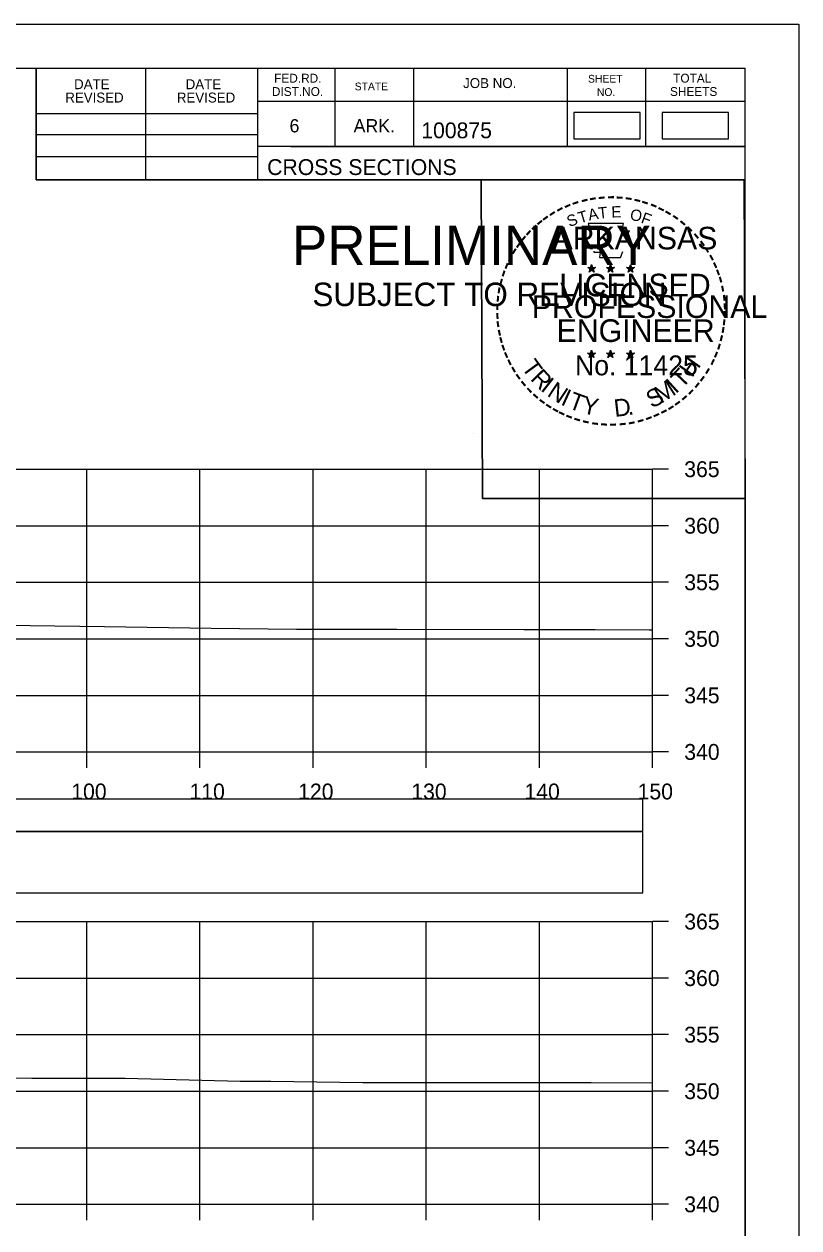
# Model space of a CAD drawing. Extents: x 1368122 to 1710785, y 373130 to 557566.
# Drawn here: x 1368783.3 to 1368851.8, y 375157.3 to 375263.7 of the extents above; entities that cross this region are included whole.
import ezdxf

# ---------------------------------------------------------------- set-up
doc = ezdxf.new("R2010")
doc.units = 0
for name, color, linetype in [('R_Alt Surface', 7, 'Continuous'), ('R_Axis', 7, 'Continuous'), ('R_Axis Annot', 7, 'Continuous'), ('R_Border', 7, 'Continuous'), ('R_Border PE', 7, 'Continuous'), ('R_Border Prem', 7, 'Continuous'), ('R_Drive', 7, 'Continuous'), ('R_Exist Surface', 7, 'Continuous'), ('R_Grid', 7, 'Continuous'), ('R_No Plot', 7, 'Continuous')]:
    doc.layers.add(name, color=color, linetype=linetype)

msp = doc.modelspace()

# ---------------------------------------------------------------- linework, layer by layer
at = {"layer": 'R_Alt Surface'}
for points in [[(1368539.73, 375192.34), (1368838.03, 375192.34), (1368838.03, 375195.16), (1368539.73, 375195.16)], [(1368539.73, 375186.88), (1368838.03, 375186.88), (1368838.03, 375192.29), (1368539.73, 375192.29)]]:
    msp.add_lwpolyline(points, close=True, dxfattribs=at)
at = {"layer": 'R_Axis'}
for p, q in [((1368838.88, 375199.35), (1368838.88, 375224.35)), ((1368840.28, 375224.35), (1368838.88, 375224.35)), ((1368840.28, 375219.35), (1368838.88, 375219.35)), ((1368840.28, 375214.35), (1368838.88, 375214.35)), ((1368840.28, 375209.35), (1368838.88, 375209.35)), ((1368840.28, 375204.35), (1368838.88, 375204.35)), ((1368538.88, 375199.35), (1368838.88, 375199.35)), ((1368788.88, 375197.95), (1368788.88, 375199.35)), ((1368798.88, 375197.95), (1368798.88, 375199.35)), ((1368808.88, 375197.95), (1368808.88, 375199.35)), ((1368818.88, 375197.95), (1368818.88, 375199.35)), ((1368828.88, 375197.95), (1368828.88, 375199.35)), ((1368838.88, 375197.95), (1368838.88, 375199.35)), ((1368840.28, 375199.35), (1368838.88, 375199.35)), ((1368838.88, 375159.35), (1368838.88, 375184.35)), ((1368840.28, 375184.35), (1368838.88, 375184.35)), ((1368840.28, 375179.35), (1368838.88, 375179.35)), ((1368840.28, 375174.35), (1368838.88, 375174.35)), ((1368840.28, 375169.35), (1368838.88, 375169.35)), ((1368840.28, 375164.35), (1368838.88, 375164.35)), ((1368538.88, 375159.35), (1368838.88, 375159.35)), ((1368788.88, 375157.95), (1368788.88, 375159.35)), ((1368798.88, 375157.95), (1368798.88, 375159.35)), ((1368808.88, 375157.95), (1368808.88, 375159.35)), ((1368818.88, 375157.95), (1368818.88, 375159.35)), ((1368828.88, 375157.95), (1368828.88, 375159.35)), ((1368838.88, 375157.95), (1368838.88, 375159.35)), ((1368840.28, 375159.35), (1368838.88, 375159.35))]:
    msp.add_line(p, q, dxfattribs=at)
at = {"layer": 'R_Border'}
for p, q in [((1368530.88, 375259.81), (1368847.06, 375259.81)), ((1368784.42, 375249.93), (1368784.42, 375259.81)), ((1368794.1, 375249.93), (1368794.1, 375259.81)), ((1368803.96, 375259.81), (1368803.96, 375249.93)), ((1368810.8, 375259.81), (1368810.8, 375252.87)), ((1368817.74, 375259.81), (1368817.74, 375252.87)), ((1368831.32, 375259.81), (1368831.32, 375252.87)), ((1368838.26, 375259.81), (1368838.26, 375252.87)), ((1368847.06, 375054.35), (1368847.06, 375259.81)), ((1368847.06, 375256.87), (1368803.96, 375256.87)), ((1368847.06, 375256.89), (1368847.06, 375256.89)), ((1368784.42, 375255.79), (1368803.96, 375255.79)), ((1368784.42, 375253.93), (1368803.96, 375253.93)), ((1368847.06, 375252.87), (1368803.96, 375252.87)), ((1368806.92, 375252.87), (1368847.06, 375252.87)), ((1368784.42, 375251.99), (1368803.96, 375251.99)), ((1368847.06, 375249.93), (1368784.42, 375249.93))]:
    msp.add_line(p, q, dxfattribs=at)
at = {"layer": 'R_Border PE'}
for p, q in [((1368833.15, 375242.19), (1368833.49, 375242.08)), ((1368833.15, 375242.19), (1368833.4, 375242.14)), ((1368833.15, 375242.19), (1368833.38, 375242.06)), ((1368833.28, 375241.78), (1368833.49, 375242.08)), ((1368833.28, 375241.78), (1368833.4, 375242.02)), ((1368833.28, 375241.78), (1368833.49, 375242)), ((1368833.49, 375242.44), (1368833.45, 375242.19)), ((1368833.49, 375242.08), (1368833.49, 375242.44)), ((1368833.49, 375242.44), (1368833.54, 375242.19)), ((1368833.84, 375242.19), (1368833.49, 375242.08)), ((1368833.71, 375241.78), (1368833.49, 375242.08)), ((1368833.71, 375241.78), (1368833.49, 375241.99)), ((1368833.84, 375242.19), (1368833.56, 375242.14)), ((1368833.71, 375241.78), (1368833.57, 375242.07)), ((1368833.84, 375242.19), (1368833.64, 375242.08)), ((1368834.82, 375242.19), (1368835.16, 375242.08)), ((1368834.82, 375242.19), (1368835.07, 375242.14)), ((1368834.82, 375242.19), (1368835.05, 375242.06)), ((1368834.95, 375241.78), (1368835.16, 375242.08)), ((1368834.95, 375241.78), (1368835.07, 375242.02)), ((1368834.95, 375241.78), (1368835.16, 375242)), ((1368835.16, 375242.44), (1368835.12, 375242.19)), ((1368835.16, 375242.08), (1368835.16, 375242.44)), ((1368835.16, 375242.44), (1368835.21, 375242.19)), ((1368835.51, 375242.19), (1368835.16, 375242.08)), ((1368835.38, 375241.78), (1368835.16, 375242.08)), ((1368835.38, 375241.78), (1368835.16, 375241.99)), ((1368835.51, 375242.19), (1368835.23, 375242.14)), ((1368835.38, 375241.78), (1368835.24, 375242.07)), ((1368835.51, 375242.19), (1368835.31, 375242.08)), ((1368836.58, 375242.17), (1368836.93, 375242.06)), ((1368836.58, 375242.17), (1368836.83, 375242.13)), ((1368836.58, 375242.17), (1368836.82, 375242.05)), ((1368836.71, 375241.77), (1368836.93, 375242.06)), ((1368836.71, 375241.77), (1368836.84, 375242.01)), ((1368836.71, 375241.77), (1368836.93, 375241.98)), ((1368836.93, 375242.43), (1368836.89, 375242.18)), ((1368836.93, 375242.06), (1368836.93, 375242.43)), ((1368836.93, 375242.43), (1368836.98, 375242.18)), ((1368837.28, 375242.17), (1368836.93, 375242.06)), ((1368837.14, 375241.77), (1368836.93, 375242.06)), ((1368837.14, 375241.77), (1368836.93, 375241.98)), ((1368837.28, 375242.17), (1368836.99, 375242.13)), ((1368837.14, 375241.77), (1368837, 375242.06)), ((1368837.28, 375242.17), (1368837.07, 375242.07)), ((1368833.14, 375234.61), (1368833.49, 375234.5)), ((1368833.14, 375234.61), (1368833.39, 375234.57)), ((1368833.14, 375234.61), (1368833.38, 375234.49)), ((1368833.27, 375234.21), (1368833.49, 375234.5)), ((1368833.27, 375234.21), (1368833.4, 375234.45)), ((1368833.27, 375234.21), (1368833.49, 375234.42)), ((1368833.49, 375234.87), (1368833.45, 375234.62)), ((1368833.49, 375234.5), (1368833.49, 375234.87)), ((1368833.49, 375234.87), (1368833.54, 375234.62)), ((1368833.84, 375234.61), (1368833.49, 375234.5)), ((1368833.7, 375234.21), (1368833.49, 375234.5)), ((1368833.7, 375234.21), (1368833.49, 375234.42)), ((1368833.84, 375234.61), (1368833.55, 375234.56)), ((1368833.7, 375234.21), (1368833.57, 375234.5)), ((1368833.84, 375234.61), (1368833.63, 375234.51)), ((1368834.81, 375234.61), (1368835.16, 375234.5)), ((1368834.81, 375234.61), (1368835.06, 375234.57)), ((1368834.81, 375234.61), (1368835.05, 375234.49)), ((1368834.94, 375234.21), (1368835.16, 375234.5)), ((1368834.94, 375234.21), (1368835.07, 375234.45)), ((1368834.94, 375234.21), (1368835.16, 375234.42)), ((1368835.16, 375234.87), (1368835.12, 375234.62)), ((1368835.16, 375234.5), (1368835.16, 375234.87)), ((1368835.16, 375234.87), (1368835.21, 375234.62)), ((1368835.51, 375234.61), (1368835.16, 375234.5)), ((1368835.37, 375234.21), (1368835.16, 375234.5)), ((1368835.37, 375234.21), (1368835.16, 375234.42)), ((1368835.51, 375234.61), (1368835.22, 375234.56)), ((1368835.37, 375234.21), (1368835.24, 375234.5)), ((1368835.51, 375234.61), (1368835.3, 375234.51)), ((1368836.58, 375234.6), (1368836.93, 375234.49)), ((1368836.58, 375234.6), (1368836.83, 375234.56)), ((1368836.58, 375234.6), (1368836.81, 375234.48)), ((1368836.71, 375234.2), (1368836.93, 375234.49)), ((1368836.71, 375234.2), (1368836.84, 375234.44)), ((1368836.71, 375234.2), (1368836.92, 375234.41)), ((1368836.93, 375234.86), (1368836.89, 375234.61)), ((1368837.14, 375234.2), (1368836.92, 375234.41)), ((1368836.93, 375234.49), (1368836.93, 375234.86)), ((1368836.93, 375234.86), (1368836.98, 375234.61)), ((1368837.27, 375234.6), (1368836.93, 375234.49)), ((1368837.14, 375234.2), (1368836.93, 375234.49)), ((1368837.27, 375234.6), (1368836.99, 375234.55)), ((1368837.14, 375234.2), (1368837, 375234.49)), ((1368837.27, 375234.6), (1368837.07, 375234.5))]:
    msp.add_line(p, q, dxfattribs=at)
for points in [[(1368833.19, 375246.06), (1368833.46, 375245.24)], [(1368836.7, 375245.14), (1368836.84, 375245.43), (1368836.15, 375245.4), (1368836.3, 375246.06), (1368833.19, 375246.06)], [(1368833.68, 375243.64), (1368833.68, 375243.55), (1368834.24, 375243.54), (1368834.19, 375243.06), (1368836.06, 375243.06), (1368836.26, 375243.6)], [(1368833.49, 375242.44), (1368833.71, 375241.78), (1368833.15, 375242.19), (1368833.84, 375242.19), (1368833.28, 375241.78), (1368833.49, 375242.44)], [(1368835.16, 375242.44), (1368835.38, 375241.78), (1368834.82, 375242.19), (1368835.51, 375242.19), (1368834.95, 375241.78), (1368835.16, 375242.44)], [(1368836.93, 375242.43), (1368837.14, 375241.77), (1368836.58, 375242.17), (1368837.28, 375242.17), (1368836.71, 375241.77), (1368836.93, 375242.43)], [(1368833.49, 375234.87), (1368833.7, 375234.21), (1368833.14, 375234.61), (1368833.84, 375234.61), (1368833.27, 375234.21), (1368833.49, 375234.87)], [(1368835.16, 375234.87), (1368835.37, 375234.21), (1368834.81, 375234.61), (1368835.51, 375234.61), (1368834.94, 375234.21), (1368835.16, 375234.87)], [(1368836.93, 375234.86), (1368837.14, 375234.2), (1368836.58, 375234.6), (1368837.27, 375234.6), (1368836.71, 375234.2), (1368836.93, 375234.86)]]:
    msp.add_lwpolyline(points, dxfattribs=at)
for centre, radius in [((1368833.49, 375242.07), 0.172), ((1368833.49, 375242.07), 0.145), ((1368833.49, 375242.07), 0.116), ((1368833.49, 375242.07), 0.0991), ((1368833.49, 375242.07), 0.0747), ((1368833.49, 375242.07), 0.0495), ((1368833.49, 375242.07), 0.0296), ((1368835.16, 375242.07), 0.172), ((1368835.16, 375242.07), 0.145), ((1368835.16, 375242.07), 0.116), ((1368835.16, 375242.07), 0.0991), ((1368835.16, 375242.07), 0.0747), ((1368835.16, 375242.07), 0.0495), ((1368835.16, 375242.07), 0.0296), ((1368836.93, 375242.06), 0.172), ((1368836.93, 375242.06), 0.145), ((1368836.93, 375242.06), 0.116), ((1368836.93, 375242.06), 0.0991), ((1368836.93, 375242.06), 0.0747), ((1368836.93, 375242.06), 0.0495), ((1368836.93, 375242.06), 0.0296), ((1368833.49, 375234.5), 0.172), ((1368833.49, 375234.5), 0.145), ((1368833.49, 375234.5), 0.116), ((1368833.49, 375234.5), 0.0991), ((1368833.49, 375234.5), 0.0747), ((1368833.49, 375234.5), 0.0495), ((1368833.49, 375234.5), 0.0296), ((1368835.16, 375234.5), 0.172), ((1368835.16, 375234.5), 0.145), ((1368835.16, 375234.5), 0.116), ((1368835.16, 375234.5), 0.0991), ((1368835.16, 375234.5), 0.0747), ((1368835.16, 375234.5), 0.0495), ((1368835.16, 375234.5), 0.0296), ((1368836.93, 375234.49), 0.172), ((1368836.93, 375234.49), 0.145), ((1368836.93, 375234.49), 0.116), ((1368836.93, 375234.49), 0.0991), ((1368836.93, 375234.49), 0.0747), ((1368836.93, 375234.49), 0.0495), ((1368836.93, 375234.49), 0.0296)]:
    msp.add_circle(centre, radius, dxfattribs=at)
at = {"layer": 'R_Drive'}
for points in [[(1368831.93, 375253.57), (1368837.77, 375253.57), (1368837.77, 375255.88), (1368831.93, 375255.88)], [(1368839.74, 375253.57), (1368845.58, 375253.57), (1368845.58, 375255.88), (1368839.74, 375255.88)]]:
    msp.add_lwpolyline(points, close=True, dxfattribs=at)
at = {"layer": 'R_Exist Surface'}
for points in [[(1368731.13, 375212.31), (1368743.96, 375211.83), (1368745.31, 375211.78), (1368746.01, 375211.76), (1368746.56, 375211.75), (1368752.58, 375211.61), (1368753.7, 375211.48), (1368759.44, 375211.17), (1368762.31, 375211.12), (1368769.98, 375210.82), (1368772.66, 375210.76), (1368774.76, 375210.66), (1368783.88, 375210.54), (1368790.45, 375210.45), (1368799.86, 375210.29), (1368807.4, 375210.2), (1368816.28, 375210.2), (1368827.49, 375210.17), (1368833.8, 375210.17), (1368838.57, 375210.14), (1368838.88, 375210.14)], [(1368740.7, 375171.86), (1368747.9, 375171.57), (1368763.84, 375171.02), (1368766.69, 375170.91), (1368767.25, 375170.93), (1368769.25, 375170.84), (1368770.02, 375170.82), (1368774.17, 375170.74), (1368779.38, 375170.58), (1368784.03, 375170.5), (1368792.26, 375170.51), (1368802.45, 375170.23), (1368805.14, 375170.23), (1368813.29, 375170.11), (1368819.21, 375170.11), (1368819.86, 375170.11), (1368833.46, 375170.12), (1368838.88, 375170.08)]]:
    msp.add_lwpolyline(points, dxfattribs=at)
at = {"layer": 'R_Grid'}
for p, q in [((1368538.88, 375224.35), (1368838.88, 375224.35)), ((1368788.88, 375199.35), (1368788.88, 375224.35)), ((1368798.88, 375199.35), (1368798.88, 375224.35)), ((1368808.88, 375199.35), (1368808.88, 375224.35)), ((1368818.88, 375199.35), (1368818.88, 375224.35)), ((1368828.88, 375199.35), (1368828.88, 375224.35)), ((1368838.88, 375199.35), (1368838.88, 375224.35)), ((1368538.88, 375219.35), (1368838.88, 375219.35)), ((1368538.88, 375214.35), (1368838.88, 375214.35)), ((1368538.88, 375209.35), (1368838.88, 375209.35)), ((1368538.88, 375204.35), (1368838.88, 375204.35)), ((1368538.88, 375199.35), (1368838.88, 375199.35)), ((1368538.88, 375184.35), (1368838.88, 375184.35)), ((1368788.88, 375159.35), (1368788.88, 375184.35)), ((1368798.88, 375159.35), (1368798.88, 375184.35)), ((1368808.88, 375159.35), (1368808.88, 375184.35)), ((1368818.88, 375159.35), (1368818.88, 375184.35)), ((1368828.88, 375159.35), (1368828.88, 375184.35)), ((1368838.88, 375159.35), (1368838.88, 375184.35)), ((1368538.88, 375179.35), (1368838.88, 375179.35)), ((1368538.88, 375174.35), (1368838.88, 375174.35)), ((1368538.88, 375169.35), (1368838.88, 375169.35)), ((1368538.88, 375164.35), (1368838.88, 375164.35)), ((1368538.88, 375159.35), (1368838.88, 375159.35))]:
    msp.add_line(p, q, dxfattribs=at)
at = {"layer": 'R_No Plot'}
for p, q in [((1368518.48, 375263.71), (1368851.81, 375263.71)), ((1368823.09, 375227.48), (1368823.09, 375227.48))]:
    msp.add_line(p, q, dxfattribs=at)
for points in [[(1368518.47, 375263.71), (1368851.81, 375263.71), (1368851.81, 375050.37), (1368518.47, 375050.37)], [(1368764.8, 375259.81), (1368784.42, 375259.81), (1368784.42, 375249.93), (1368800.53, 375249.93), (1368823.73, 375249.93), (1368823.85, 375221.77), (1368847.06, 375221.77), (1368847.06, 375054.35), (1368530.88, 375054.35), (1368530.88, 375259.81)], [(1368823.73, 375249.93), (1368846.94, 375249.93), (1368847.06, 375221.77), (1368823.85, 375221.77)]]:
    msp.add_lwpolyline(points, close=True, dxfattribs=at)

# ---------------------------------------------------------------- texts
at = {"layer": 'R_Axis Annot'}
for s, p in [('365', (1368841.68, 375223.65)), ('360', (1368841.68, 375218.65)), ('355', (1368841.68, 375213.65)), ('350', (1368841.68, 375208.65)), ('345', (1368841.68, 375203.65)), ('340', (1368841.68, 375198.65)), ('100', (1368787.51, 375195.15)), ('110', (1368797.96, 375195.15)), ('120', (1368807.56, 375195.15)), ('130', (1368817.56, 375195.15)), ('140', (1368827.56, 375195.15)), ('150', (1368837.56, 375195.15)), ('365', (1368841.68, 375183.65)), ('360', (1368841.68, 375178.65)), ('355', (1368841.68, 375173.65)), ('350', (1368841.68, 375168.65)), ('345', (1368841.68, 375163.65)), ('340', (1368841.68, 375158.65))]:
    msp.add_text(s, height=1.4, dxfattribs=at).set_placement(p)
at = {"layer": 'R_Border'}
for s, height, p in [('DATE', 0.879, (1368787.76, 375257.95)), ('DATE', 0.879, (1368797.62, 375257.95)), ('FED.RD.', 0.782, (1368805.44, 375258.53)), ('STATE', 0.684, (1368812.56, 375257.85)), ('JOB NO.', 0.879, (1368822.14, 375258.05)), ('SHEET', 0.684, (1368833.18, 375258.53)), ('TOTAL', 0.782, (1368840.7, 375258.53)), ('REVISED', 0.879, (1368786.98, 375256.77)), ('REVISED', 0.879, (1368796.84, 375256.77)), ('DIST.NO.', 0.782, (1368805.24, 375257.35)), ('NO.', 0.684, (1368833.96, 375257.35)), ('SHEETS', 0.782, (1368840.42, 375257.35)), ('6', 1.17, (1368806.8, 375254.13)), ('ARK.', 1.172, (1368812.46, 375254.13)), ('100875', 1.4, (1368818.44, 375253.61)), ('CROSS SECTIONS', 1.4, (1368804.82, 375250.36))]:
    msp.add_text(s, height=height, rotation=360, dxfattribs=at).set_placement(p)
at = {"layer": 'R_Border PE'}
for s, height, rotation, p in [('-', 1.6, 19.1761, (1368831.93, 375247.19)), ('-', 1.6, 13.6301, (1368832.68, 375247.43)), ('-', 1.6, 10.2193, (1368833.36, 375247.59)), ('-', 1.6, 5.8968, (1368834.09, 375247.7)), ('-', 1.6, 0.1862, (1368834.86, 375247.78)), ('-', 1.6, 357.743, (1368835.59, 375247.76)), ('-', 1.6, 352.1617, (1368836.33, 375247.71)), ('-', 1.6, 347.2049, (1368837.05, 375247.59)), ('-', 1.6, 342.3362, (1368837.68, 375247.44)), ('-', 1.6, 337.8551, (1368838.42, 375247.22)), ('-', 1.6, 36.2317, (1368829.49, 375245.84)), ('-', 1.6, 34.0636, (1368830.07, 375246.24)), ('-', 1.6, 28.7918, (1368830.67, 375246.61)), ('-', 1.6, 24.3072, (1368831.3, 375246.92)), ('S', 1, 21.594, (1368831.54, 375245.74)), ('T', 1, 16.4036, (1368832.46, 375246.07)), ('A', 1, 11.2132, (1368833.28, 375246.32)), ('T', 1, 6.0228, (1368834.13, 375246.49)), ('E', 1, 0.8323, (1368835.24, 375246.6)), ('O', 1, 350.4515, (1368836.84, 375246.39)), ('F', 1, 340.0707, (1368837.79, 375246.16)), ('-', 1.6, 334.1211, (1368839.05, 375246.94)), ('-', 1.6, 329.6409, (1368839.63, 375246.66)), ('-', 1.6, 325.8627, (1368840.27, 375246.3)), ('-', 1.6, 42.9622, (1368828.58, 375245.05)), ('-', 1.6, 38.9507, (1368829.02, 375245.46)), ('ARKANSAS', 2, 360, (1368830.04, 375243.78)), ('-', 1.6, 320.5297, (1368840.88, 375245.87)), ('-', 1.6, 315.5786, (1368841.48, 375245.39)), ('-', 1.6, 50.6142, (1368827.73, 375244.08)), ('-', 1.6, 48.423, (1368828.14, 375244.57)), ('-', 1.6, 309.8797, (1368842.05, 375244.84)), ('-', 1.6, 58.0706, (1368826.99, 375242.99)), ('-', 1.6, 54.2325, (1368827.32, 375243.51)), ('-', 1.6, 306.6522, (1368842.58, 375244.23)), ('-', 1.4, 303.6753, (1368843.06, 375243.67)), ('-', 1.6, 67.7743, (1368826.42, 375241.76)), ('-', 1.6, 62.8713, (1368826.68, 375242.37)), ('-', 1.6, 299.6684, (1368843.38, 375243.06)), ('-', 1.6, 294.6628, (1368843.7, 375242.45)), ('-', 1.6, 72.3945, (1368826.2, 375241.13)), ('LICENSED', 2, 360, (1368830.64, 375239.63)), ('DWB', 0.01, 360, (1368833.48, 375242.07)), ('DWB', 0.01, 360, (1368835.15, 375242.07)), ('DWB', 0.01, 360, (1368836.92, 375242.06)), ('-', 1.6, 290.5728, (1368843.96, 375241.87)), ('-', 1.6, 81.2013, (1368825.87, 375239.71)), ('-', 1.6, 75.461, (1368826.01, 375240.42)), ('-', 1.6, 285.1233, (1368844.2, 375241.29)), ('-', 1.6, 280.5493, (1368844.4, 375240.55)), ('-', 1.6, 85.1863, (1368825.8, 375239.01)), ('PROFESSIONAL', 2, 360, (1368828.21, 375237.72)), ('-', 1.6, 276.5962, (1368844.56, 375239.78)), ('-', 1.6, 89.0622, (1368825.77, 375238.31)), ('-', 1.6, 274.3301, (1368844.62, 375239.06)), ('-', 1.6, 269.9407, (1368844.65, 375238.43)), ('-', 1.6, 94.1959, (1368825.81, 375237.59)), ('-', 1.6, 98.9479, (1368825.88, 375236.92)), ('ENGINEER', 2, 360, (1368830.4, 375235.6)), ('-', 1.6, 263.5172, (1368844.63, 375237.76)), ('-', 1.6, 101.7149, (1368826.02, 375236.19)), ('-', 1.6, 255.7626, (1368844.45, 375236.43)), ('-', 1.6, 260.9953, (1368844.56, 375237.11)), ('-', 1.6, 105.4578, (1368826.18, 375235.59)), ('-', 1.6, 109.0874, (1368826.39, 375234.96)), ('-', 1.6, 252.8681, (1368844.27, 375235.71)), ('-', 1.6, 114.0643, (1368826.65, 375234.37)), ('-', 1.6, 115.7289, (1368826.95, 375233.75)), ('T', 1.54, 306.0406, (1368827.25, 375233.34)), ('No. 11425', 1.757, 360, (1368832.03, 375232.65)), ('DWB', 0.01, 360, (1368833.48, 375234.5)), ('DWB', 0.01, 360, (1368835.15, 375234.5)), ('DWB', 0.01, 360, (1368836.91, 375234.49)), ('H', 1.54, 54.6088, (1368842.37, 375232.38)), ('-', 1.6, 244.6197, (1368843.79, 375234.41)), ('-', 1.6, 247.8887, (1368844.05, 375235.04)), ('-', 1.6, 120.4471, (1368827.31, 375233.16)), ('R', 1.54, 314.005, (1368828.01, 375232.29)), ('T', 1.54, 46.6444, (1368841.48, 375231.43)), ('-', 1.6, 239.0712, (1368843.39, 375233.65)), ('-', 1.6, 125.8934, (1368827.71, 375232.6)), ('-', 1.6, 130.7181, (1368828.17, 375232.05)), ('I', 1.54, 321.9694, (1368828.91, 375231.36)), ('N', 1.54, 326.5002, (1368829.48, 375230.89)), ('M', 1.54, 32.6563, (1368839.63, 375230.11)), ('I', 1.54, 42.1136, (1368840.92, 375230.96)), ('-', 1.6, 231.2538, (1368842.56, 375232.44)), ('-', 1.6, 233.8452, (1368842.99, 375233)), ('-', 1.6, 134.2238, (1368828.69, 375231.5)), ('-', 1.6, 138.9338, (1368829.22, 375231.04)), ('I', 1.54, 335.3603, (1368830.69, 375230.1)), ('T', 1.54, 339.8912, (1368831.35, 375229.78)), ('Y', 1.54, 347.8556, (1368832.57, 375229.33)), ('S', 1.54, 26.9312, (1368838.8, 375229.7)), ('-', 1.6, 221.0851, (1368841.56, 375231.36)), ('-', 1.6, 225.7653, (1368842.08, 375231.87)), ('-', 1.6, 144.6463, (1368829.77, 375230.63)), ('-', 1.6, 148.0898, (1368830.33, 375230.26)), ('-', 1.6, 151.5704, (1368830.91, 375229.94)), ('D', 1.54, 6.3969, (1368835.55, 375228.97)), ('-', 1.6, 212.2491, (1368840.48, 375230.5)), ('-', 1.6, 215.7363, (1368841.01, 375230.89)), ('-', 1.6, 154.6002, (1368831.43, 375229.69)), ('-', 1.6, 158.5612, (1368832.06, 375229.44)), ('-', 1.6, 162.7983, (1368832.74, 375229.22)), ('-', 1.6, 167.5555, (1368833.46, 375229.06)), ('.', 1.54, 13.7642, (1368836.74, 375229.1)), ('-', 1.6, 195.4743, (1368838, 375229.32)), ('-', 1.6, 200.7184, (1368838.67, 375229.57)), ('-', 1.6, 204.2516, (1368839.29, 375229.84)), ('-', 1.6, 207.3568, (1368839.92, 375230.16)), ('-', 1.6, 173.1155, (1368834.23, 375228.95)), ('-', 1.6, 176.5183, (1368834.98, 375228.9)), ('-', 1.6, 181.5918, (1368835.72, 375228.92)), ('-', 1.6, 185.8167, (1368836.53, 375228.99)), ('-', 1.6, 191.2858, (1368837.27, 375229.12))]:
    msp.add_text(s, height=height, rotation=rotation, dxfattribs=at).set_placement(p)
at = {"layer": 'R_Border Prem'}
for s, height, p in [('PRELIMINARY', 3.5, (1368807.01, 375242.39)), ('DWB', 0.01, (1368807.76, 375244.24)), ('SUBJECT TO REVISION', 2.0751, (1368808.82, 375238.77))]:
    msp.add_text(s, height=height, rotation=360, dxfattribs=at).set_placement(p)

doc.saveas('drawing.dxf')
